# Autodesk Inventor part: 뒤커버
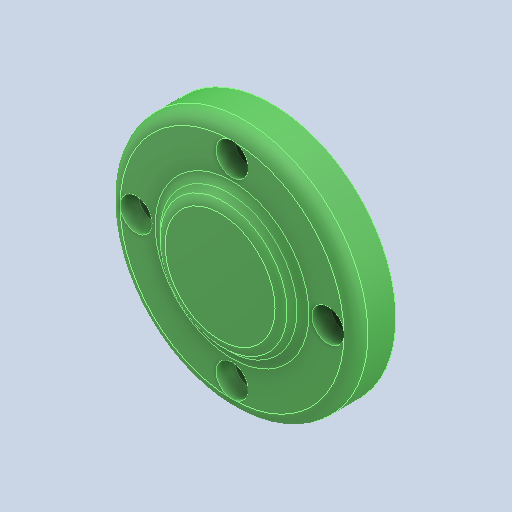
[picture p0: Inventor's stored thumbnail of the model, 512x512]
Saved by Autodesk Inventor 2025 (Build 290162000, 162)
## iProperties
Created: 2025-08
Part Number: 뒤커버
Material: 알루미늄 6061
Document SubType Name: Modeling
Designer: infra02
Density: 2.71 g/cm^3
Appearance: 기본값
Author: jhkim
Sending System: Autodesk Inventor 2026
Preprocessor: ST-DEVELOPER v20.1
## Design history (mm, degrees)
feature "솔리드1"
node "솔리드2"
